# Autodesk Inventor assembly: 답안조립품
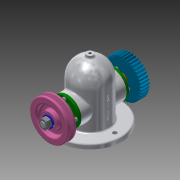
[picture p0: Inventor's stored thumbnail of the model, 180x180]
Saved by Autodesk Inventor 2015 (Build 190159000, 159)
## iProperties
Created: 2019-11
Part Number: 답안조립품
Document SubType Name: Assembly
Designer: 1010101
Author: 1010101
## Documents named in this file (14)
- C:\Users\1010101\Desktop\491104V1031\답안조립품.iam
- C:\Users\1010101\Desktop\491104V1031\V-벨트풀리.ipt
- V-벨트풀리.ipt
- C:\Users\1010101\Desktop\491104V1031\너트 M12x1.25.ipt
- C:\Users\1010101\Desktop\491104V1031\베어링 6203.ipt
- C:\Users\1010101\Desktop\491104V1031\본체.ipt
- C:\Users\1010101\Desktop\491104V1031\볼트 M4.ipt
- C:\Users\1010101\Desktop\491104V1031\부시.ipt
- C:\Users\1010101\Desktop\491104V1031\스퍼기어.ipt
- C:\Users\1010101\Desktop\491104V1031\오일 실 26 38 8.ipt
- C:\Users\1010101\Desktop\491104V1031\와셔 12x24.ipt
- C:\Users\1010101\Desktop\491104V1031\축.ipt
- C:\Users\1010101\Desktop\491104V1031\커버.ipt
- C:\Users\1010101\Desktop\491104V1031\키 5x5x12.ipt
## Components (1 placed, 1 different names)
1. V-벨트풀리:1 — 각도:3
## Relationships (1: Angle 1)
- 각도:3 [Angle]: V-벨트풀리:1
